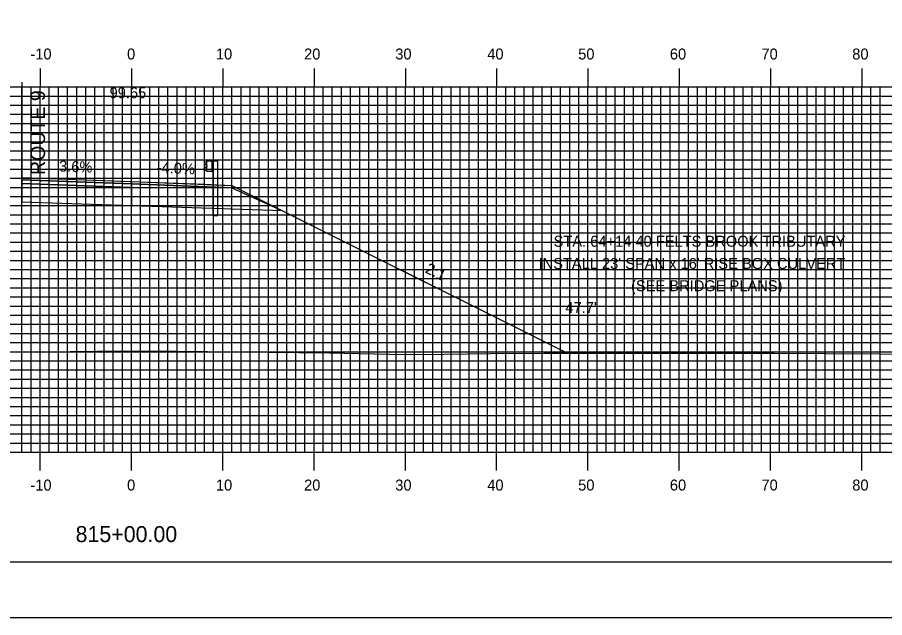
# Model space of a CAD drawing. Extents: x 2846 to 3190, y -1658 to -1438.
# Drawn here: x 2999.7 to 3094.7, y -1657.7 to -1592 of the extents above; entities that cross this region are included whole.
import ezdxf

# ---------------------------------------------------------------- set-up
doc = ezdxf.new("R2010")
doc.units = 0
for name, color, linetype in [('ANNOTATION', 7, 'Continuous'), ('BORDER', 7, 'Continuous'), ('D_Guardrail_Beam_Rt', 7, 'Continuous'), ('D_Roadway_Centerline', 7, 'Continuous'), ('D_Roadway_Centerline_Text', 7, 'Continuous'), ('D_Roadway_Edge_Shoulder', 7, 'Continuous'), ('D_Roadway_Edge_TW', 7, 'Continuous'), ('D_Roadway_Pavement', 7, 'Continuous'), ('D_Roadway_SlopeLines', 7, 'Continuous'), ('D_Roadway_SubGrade', 7, 'Continuous'), ('D_Text_Standard', 7, 'Continuous'), ('H_V ANNOTATION', 7, 'Continuous'), ('MAJOR', 7, 'Continuous'), ('MINOR', 7, 'Continuous'), ('PLOT BOUNDARY', 7, 'Continuous'), ('S_Roadway_Centerline', 7, 'Continuous')]:
    doc.layers.add(name, color=color, linetype=linetype)

msp = doc.modelspace()

# ---------------------------------------------------------------- linework, layer by layer
at = {"layer": 'BORDER'}
msp.add_lwpolyline([(2862.613, -1651.604), (3182.613, -1651.604), (3182.613, -1441.604), (2862.613, -1441.604)], close=True, dxfattribs=at)
at = {"layer": 'D_Guardrail_Beam_Rt'}
for p, q in [((3020.394, -1607.794), (3020.25, -1607.894)), ((3020.25, -1608.037), (3020.446, -1608.173)), ((3020.484, -1607.773), (3020.41, -1607.787)), ((3020.479, -1608.237), (3020.479, -1608.308)), ((3020.484, -1607.689), (3021.171, -1607.689)), ((3020.484, -1608.856), (3020.484, -1607.689)), ((3021.005, -1607.689), (3021.005, -1608.856)), ((3021.109, -1607.689), (3021.109, -1608.856)), ((3021.171, -1607.689), (3021.642, -1607.689)), ((3021.171, -1607.689), (3021.171, -1608.856)), ((3021.642, -1607.689), (3021.642, -1613.689)), ((3020.446, -1608.372), (3020.25, -1608.508)), ((3020.25, -1608.651), (3020.394, -1608.751)), ((3020.41, -1608.758), (3020.484, -1608.773)), ((3021.171, -1608.856), (3020.484, -1608.856)), ((3021.15, -1613.689), (3021.15, -1608.856)), ((3021.15, -1613.689), (3021.642, -1613.689))]:
    msp.add_line(p, q, dxfattribs=at)
for centre, major_axis, start_param, end_param in [((3020.301, -1607.965), (-0.0877, 0), 5.323254, 7.243116), ((3020.418, -1607.828), (-0.0417, 0), 4.907132, 5.323254), ((3020.4, -1608.237), (0.0789, 0), 0, 0.959931), ((3020.4, -1608.308), (0.0789, 0), 5.323254, 6.283185), ((3020.301, -1608.58), (-0.0877, 0), 5.323254, 7.243116), ((3020.418, -1608.717), (-0.0417, 0), 0.959931, 1.376053)]:
    msp.add_ellipse(centre, major_axis=major_axis, ratio=0.995501, start_param=start_param, end_param=end_param, dxfattribs=at)
at = {"layer": 'D_Roadway_Centerline'}
msp.add_lwpolyline([(3000.213, -1609.518), (3012.052, -1609.947), (3012.213, -1609.953), (3020.105, -1610.268), (3020.213, -1610.273), (3023.172, -1610.391), (3023.213, -1610.393), (3028.69, -1613.131), (3028.764, -1613.168), (3029.195, -1613.384), (3059.956, -1628.764)], dxfattribs=at)
at = {"layer": 'D_Roadway_Edge_Shoulder'}
for points in [[(3012.213, -1609.953), (3023.213, -1610.393), (3023.213, -1610.643), (3012.213, -1610.203)], [(3012.213, -1609.953), (3020.213, -1610.273), (3020.213, -1610.273), (3023.213, -1610.393), (3023.213, -1610.643), (3012.213, -1610.203)], [(3012.213, -1609.953), (3020.213, -1610.273), (3020.213, -1610.273), (3023.213, -1610.393), (3023.213, -1610.643), (3012.213, -1610.203)], [(3012.213, -1609.953), (3023.213, -1610.393), (3023.213, -1610.643), (3012.213, -1610.203)], [(3012.213, -1609.953), (3023.213, -1610.393), (3023.213, -1610.643), (3012.213, -1610.203)]]:
    msp.add_lwpolyline(points, close=True, dxfattribs=at)
at = {"layer": 'D_Roadway_Edge_TW'}
msp.add_lwpolyline([(3000.213, -1609.518), (3012.213, -1609.953), (3012.213, -1610.203), (3000.213, -1609.768)], close=True, dxfattribs=at)
msp.add_lwpolyline([(3000.213, -1609.518), (3012.213, -1609.953), (3012.213, -1610.203), (3000.213, -1609.768)], close=True, dxfattribs=at)
msp.add_lwpolyline([(3000.213, -1609.518), (3012.213, -1609.953), (3012.213, -1610.203), (3000.213, -1609.768)], close=True, dxfattribs=at)
msp.add_lwpolyline([(3000.213, -1609.518), (3012.213, -1609.953), (3012.213, -1610.203), (3000.213, -1609.768)], close=True, dxfattribs=at)
at = {"layer": 'D_Roadway_Pavement'}
msp.add_lwpolyline([(3000.213, -1609.768), (3012.213, -1610.203), (3012.213, -1610.619), (3000.213, -1610.185)], close=True, dxfattribs=at)
msp.add_lwpolyline([(3000.213, -1609.768), (3012.213, -1610.203), (3012.213, -1610.619), (3000.213, -1610.185)], close=True, dxfattribs=at)
msp.add_lwpolyline([(3000.213, -1609.768), (3012.213, -1610.203), (3012.213, -1610.619), (3000.213, -1610.185)], close=True, dxfattribs=at)
msp.add_lwpolyline([(3000.213, -1609.768), (3012.213, -1610.203), (3012.213, -1610.619), (3000.213, -1610.185)], close=True, dxfattribs=at)
msp.add_lwpolyline([(3012.213, -1610.203), (3012.213, -1610.619)], dxfattribs=at)
msp.add_lwpolyline([(3012.213, -1610.203), (3012.213, -1610.619)], dxfattribs=at)
msp.add_lwpolyline([(3012.213, -1610.203), (3012.213, -1610.619)], dxfattribs=at)
msp.add_lwpolyline([(3012.213, -1610.203), (3012.213, -1610.619)], dxfattribs=at)
msp.add_lwpolyline([(3012.213, -1610.203), (3012.213, -1610.619)], dxfattribs=at)
msp.add_lwpolyline([(3012.213, -1610.203), (3012.213, -1610.619)], dxfattribs=at)
msp.add_lwpolyline([(3012.213, -1610.203), (3012.213, -1610.619)], dxfattribs=at)
msp.add_lwpolyline([(3012.213, -1610.203), (3012.213, -1610.619)], dxfattribs=at)
msp.add_lwpolyline([(3012.213, -1610.203), (3012.213, -1610.619)], dxfattribs=at)
msp.add_lwpolyline([(3012.213, -1610.203), (3012.213, -1610.619)], dxfattribs=at)
msp.add_lwpolyline([(3012.213, -1610.203), (3012.213, -1610.619)], dxfattribs=at)
msp.add_lwpolyline([(3012.213, -1610.203), (3012.213, -1610.619)], dxfattribs=at)
msp.add_lwpolyline([(3012.213, -1610.203), (3012.213, -1610.619)], dxfattribs=at)
msp.add_lwpolyline([(3012.213, -1610.203), (3012.213, -1610.619)], dxfattribs=at)
at = {"layer": 'D_Roadway_SlopeLines'}
msp.add_lwpolyline([(3023.213, -1610.393), (3059.956, -1628.764)], dxfattribs=at)
msp.add_lwpolyline([(3023.213, -1610.393), (3059.956, -1628.764)], dxfattribs=at)
msp.add_lwpolyline([(3023.213, -1610.393), (3059.956, -1628.764)], dxfattribs=at)
msp.add_lwpolyline([(3023.213, -1610.393), (3059.956, -1628.764)], dxfattribs=at)
at = {"layer": 'D_Roadway_SubGrade'}
msp.add_line((3000.213, -1599.081), (3000.213, -1612.221), dxfattribs=at)
for points in [[(3000.213, -1610.185), (3012.213, -1610.619), (3012.213, -1612.619), (3000.213, -1612.221)], [(3000.213, -1610.185), (3012.213, -1610.619), (3012.213, -1612.619), (3000.213, -1612.221)], [(3000.213, -1610.185), (3012.213, -1610.619), (3012.213, -1612.619), (3000.213, -1612.221)], [(3000.213, -1610.185), (3012.213, -1610.619), (3012.213, -1612.619), (3000.213, -1612.221)], [(3012.213, -1610.619), (3012.213, -1610.203), (3023.213, -1610.643), (3023.213, -1610.393), (3028.764, -1613.168), (3012.213, -1612.619)], [(3012.213, -1610.619), (3012.213, -1610.203), (3023.213, -1610.643), (3023.213, -1610.393), (3028.764, -1613.168), (3012.213, -1612.619)], [(3012.213, -1610.619), (3012.213, -1610.203), (3023.213, -1610.643), (3023.213, -1610.393), (3028.764, -1613.168), (3012.213, -1612.619)], [(3012.213, -1610.619), (3012.213, -1610.203), (3023.213, -1610.643), (3028.764, -1613.168), (3012.213, -1612.619)], [(3012.213, -1610.619), (3012.213, -1610.203), (3023.213, -1610.643), (3023.213, -1610.393), (3028.764, -1613.168), (3012.213, -1612.619)]]:
    msp.add_lwpolyline(points, close=True, dxfattribs=at)
at = {"layer": 'MAJOR'}
for p, q in [((3002.213, -1597.6), (3002.213, -1599.604)), ((3012.213, -1597.6), (3012.213, -1599.604)), ((3022.213, -1597.6), (3022.213, -1599.604)), ((3032.213, -1597.6), (3032.213, -1599.604)), ((3042.213, -1597.6), (3042.213, -1599.604)), ((3052.213, -1597.6), (3052.213, -1599.604)), ((3062.213, -1597.6), (3062.213, -1599.604)), ((3072.213, -1597.6), (3072.213, -1599.604)), ((3082.213, -1597.6), (3082.213, -1599.604)), ((3092.213, -1597.6), (3092.213, -1599.604)), ((2872.213, -1599.604), (3152.213, -1599.604)), ((2872.213, -1599.604), (3152.213, -1599.604)), ((3002.213, -1639.604), (3002.213, -1599.604)), ((3012.213, -1639.604), (3012.213, -1599.604)), ((3022.213, -1639.604), (3022.213, -1599.604)), ((3032.213, -1639.604), (3032.213, -1599.604)), ((3042.213, -1639.604), (3042.213, -1599.604)), ((3052.213, -1639.604), (3052.213, -1599.604)), ((3062.213, -1639.604), (3062.213, -1599.604)), ((3072.213, -1639.604), (3072.213, -1599.604)), ((3082.213, -1639.604), (3082.213, -1599.604)), ((3092.213, -1639.604), (3092.213, -1599.604)), ((2872.213, -1604.604), (3152.213, -1604.604)), ((2872.213, -1609.604), (3152.213, -1609.604)), ((2872.213, -1614.604), (3152.213, -1614.604)), ((2872.213, -1619.604), (3152.213, -1619.604)), ((2872.213, -1624.604), (3152.213, -1624.604)), ((2872.213, -1629.604), (3152.213, -1629.604)), ((2872.213, -1634.604), (3152.213, -1634.604)), ((2872.213, -1639.604), (3152.213, -1639.604)), ((2872.213, -1639.604), (3152.213, -1639.604)), ((3002.213, -1641.608), (3002.213, -1639.604)), ((3012.213, -1641.608), (3012.213, -1639.604)), ((3022.213, -1641.608), (3022.213, -1639.604)), ((3032.213, -1641.608), (3032.213, -1639.604)), ((3042.213, -1641.608), (3042.213, -1639.604)), ((3052.213, -1641.608), (3052.213, -1639.604)), ((3062.213, -1641.608), (3062.213, -1639.604)), ((3072.213, -1641.608), (3072.213, -1639.604)), ((3082.213, -1641.608), (3082.213, -1639.604)), ((3092.213, -1641.608), (3092.213, -1639.604))]:
    msp.add_line(p, q, dxfattribs=at)
at = {"layer": 'MINOR'}
for p, q in [((3000.213, -1639.604), (3000.213, -1599.604)), ((3001.213, -1639.604), (3001.213, -1599.604)), ((3003.213, -1639.604), (3003.213, -1599.604)), ((3004.213, -1639.604), (3004.213, -1599.604)), ((3005.213, -1639.604), (3005.213, -1599.604)), ((3006.213, -1639.604), (3006.213, -1599.604)), ((3007.213, -1639.604), (3007.213, -1599.604)), ((3008.213, -1639.604), (3008.213, -1599.604)), ((3009.213, -1639.604), (3009.213, -1599.604)), ((3010.213, -1639.604), (3010.213, -1599.604)), ((3011.213, -1639.604), (3011.213, -1599.604)), ((3013.213, -1639.604), (3013.213, -1599.604)), ((3014.213, -1639.604), (3014.213, -1599.604)), ((3015.213, -1639.604), (3015.213, -1599.604)), ((3016.213, -1639.604), (3016.213, -1599.604)), ((3017.213, -1639.604), (3017.213, -1599.604)), ((3018.213, -1639.604), (3018.213, -1599.604)), ((3019.213, -1639.604), (3019.213, -1599.604)), ((3020.213, -1639.604), (3020.213, -1599.604)), ((3021.213, -1639.604), (3021.213, -1599.604)), ((3023.213, -1639.604), (3023.213, -1599.604)), ((3024.213, -1639.604), (3024.213, -1599.604)), ((3025.213, -1639.604), (3025.213, -1599.604)), ((3026.213, -1639.604), (3026.213, -1599.604)), ((3027.213, -1639.604), (3027.213, -1599.604)), ((3028.213, -1639.604), (3028.213, -1599.604)), ((3029.213, -1639.604), (3029.213, -1599.604)), ((3030.213, -1639.604), (3030.213, -1599.604)), ((3031.213, -1639.604), (3031.213, -1599.604)), ((3033.213, -1639.604), (3033.213, -1599.604)), ((3034.213, -1639.604), (3034.213, -1599.604)), ((3035.213, -1639.604), (3035.213, -1599.604)), ((3036.213, -1639.604), (3036.213, -1599.604)), ((3037.213, -1639.604), (3037.213, -1599.604)), ((3038.213, -1639.604), (3038.213, -1599.604)), ((3039.213, -1639.604), (3039.213, -1599.604)), ((3040.213, -1639.604), (3040.213, -1599.604)), ((3041.213, -1639.604), (3041.213, -1599.604)), ((3043.213, -1639.604), (3043.213, -1599.604)), ((3044.213, -1639.604), (3044.213, -1599.604)), ((3045.213, -1639.604), (3045.213, -1599.604)), ((3046.213, -1639.604), (3046.213, -1599.604)), ((3047.213, -1639.604), (3047.213, -1599.604)), ((3048.213, -1639.604), (3048.213, -1599.604)), ((3049.213, -1639.604), (3049.213, -1599.604)), ((3050.213, -1639.604), (3050.213, -1599.604)), ((3051.213, -1639.604), (3051.213, -1599.604)), ((3053.213, -1639.604), (3053.213, -1599.604)), ((3054.213, -1639.604), (3054.213, -1599.604)), ((3055.213, -1639.604), (3055.213, -1599.604)), ((3056.213, -1639.604), (3056.213, -1599.604)), ((3057.213, -1639.604), (3057.213, -1599.604)), ((3058.213, -1639.604), (3058.213, -1599.604)), ((3059.213, -1639.604), (3059.213, -1599.604)), ((3060.213, -1639.604), (3060.213, -1599.604)), ((3061.213, -1639.604), (3061.213, -1599.604)), ((3063.213, -1639.604), (3063.213, -1599.604)), ((3064.213, -1639.604), (3064.213, -1599.604)), ((3065.213, -1639.604), (3065.213, -1599.604)), ((3066.213, -1639.604), (3066.213, -1599.604)), ((3067.213, -1639.604), (3067.213, -1599.604)), ((3068.213, -1639.604), (3068.213, -1599.604)), ((3069.213, -1639.604), (3069.213, -1599.604)), ((3070.213, -1639.604), (3070.213, -1599.604)), ((3071.213, -1639.604), (3071.213, -1599.604)), ((3073.213, -1639.604), (3073.213, -1599.604)), ((3074.213, -1639.604), (3074.213, -1599.604)), ((3075.213, -1639.604), (3075.213, -1599.604)), ((3076.213, -1639.604), (3076.213, -1599.604)), ((3077.213, -1639.604), (3077.213, -1599.604)), ((3078.213, -1639.604), (3078.213, -1599.604)), ((3079.213, -1639.604), (3079.213, -1599.604)), ((3080.213, -1639.604), (3080.213, -1599.604)), ((3081.213, -1639.604), (3081.213, -1599.604)), ((3083.213, -1639.604), (3083.213, -1599.604)), ((3084.213, -1639.604), (3084.213, -1599.604)), ((3085.213, -1639.604), (3085.213, -1599.604)), ((3086.213, -1639.604), (3086.213, -1599.604)), ((3087.213, -1639.604), (3087.213, -1599.604)), ((3088.213, -1639.604), (3088.213, -1599.604)), ((3089.213, -1639.604), (3089.213, -1599.604)), ((3090.213, -1639.604), (3090.213, -1599.604)), ((3091.213, -1639.604), (3091.213, -1599.604)), ((3093.213, -1639.604), (3093.213, -1599.604)), ((3094.213, -1639.604), (3094.213, -1599.604)), ((2872.213, -1600.604), (3152.213, -1600.604)), ((2872.213, -1601.604), (3152.213, -1601.604)), ((2872.213, -1602.604), (3152.213, -1602.604)), ((2872.213, -1603.604), (3152.213, -1603.604)), ((2872.213, -1605.604), (3152.213, -1605.604)), ((2872.213, -1606.604), (3152.213, -1606.604)), ((2872.213, -1607.604), (3152.213, -1607.604)), ((2872.213, -1608.604), (3152.213, -1608.604)), ((2872.213, -1610.604), (3152.213, -1610.604)), ((2872.213, -1611.604), (3152.213, -1611.604)), ((2872.213, -1612.604), (3152.213, -1612.604)), ((2872.213, -1613.604), (3152.213, -1613.604)), ((2872.213, -1615.604), (3152.213, -1615.604)), ((2872.213, -1616.604), (3152.213, -1616.604)), ((2872.213, -1617.604), (3152.213, -1617.604)), ((2872.213, -1618.604), (3152.213, -1618.604)), ((2872.213, -1620.604), (3152.213, -1620.604)), ((2872.213, -1621.604), (3152.213, -1621.604)), ((2872.213, -1622.604), (3152.213, -1622.604)), ((2872.213, -1623.604), (3152.213, -1623.604)), ((2872.213, -1625.604), (3152.213, -1625.604)), ((2872.213, -1626.604), (3152.213, -1626.604)), ((2872.213, -1627.604), (3152.213, -1627.604)), ((2872.213, -1628.604), (3152.213, -1628.604)), ((2872.213, -1630.604), (3152.213, -1630.604)), ((2872.213, -1631.604), (3152.213, -1631.604)), ((2872.213, -1632.604), (3152.213, -1632.604)), ((2872.213, -1633.604), (3152.213, -1633.604)), ((2872.213, -1635.604), (3152.213, -1635.604)), ((2872.213, -1636.604), (3152.213, -1636.604)), ((2872.213, -1637.604), (3152.213, -1637.604)), ((2872.213, -1638.604), (3152.213, -1638.604))]:
    msp.add_line(p, q, dxfattribs=at)
at = {"layer": 'PLOT BOUNDARY'}
msp.add_lwpolyline([(2846.426, -1657.723), (3186.426, -1657.723), (3186.426, -1437.723), (2846.426, -1437.723)], close=True, dxfattribs=at)
at = {"layer": 'S_Roadway_Centerline'}
msp.add_lwpolyline([(2992.885, -1628.666), (3002.45, -1628.61), (3011.53, -1628.507), (3017.167, -1628.528), (3033.905, -1628.716), (3040.466, -1628.879), (3043.823, -1628.912), (3051.558, -1628.813), (3057.43, -1628.765), (3059.92, -1628.764), (3070.511, -1628.752), (3078.456, -1628.753), (3082.526, -1628.763), (3099.941, -1628.88)], dxfattribs=at)

# ---------------------------------------------------------------- texts
at = {"layer": 'ANNOTATION'}
for s, height, rotation, p in [('ROUTE 9', 1.6, 90, (3002.744, -1609.248)), ('3.6%', 1.2, 357.92822, (3004.264, -1608.864)), ('-4.0%', 1.2, 357.70938, (3014.949, -1609.016)), ('2:1', 1.2, 333.43495, (3044.294, -1619.897))]:
    msp.add_text(s, height=height, rotation=rotation, dxfattribs=at).set_placement(p)
for s, p in [('STA. 64+14.40 FELTS BROOK TRIBUTARY', (3058.451, -1617.106)), ("INSTALL 23' SPAN x 16' RISE BOX CULVERT", (3056.8, -1619.541)), ('(SEE BRIDGE PLANS)', (3066.937, -1621.976))]:
    msp.add_text(s, height=1.2, dxfattribs=at).set_placement(p)
at = {"layer": 'D_Roadway_Centerline_Text'}
msp.add_text('99.65', height=1.2, dxfattribs=at).set_placement((3009.81, -1600.847))
at = {"layer": 'D_Text_Standard'}
msp.add_text("47.7'", height=1.2, dxfattribs=at).set_placement((3059.744, -1624.358))
at = {"layer": 'H_V ANNOTATION'}
for s, height, p in [('-10', 1.2, (3001.143, -1596.604)), ('0', 1.2, (3011.731, -1596.604)), ('10', 1.2, (3021.464, -1596.604)), ('20', 1.2, (3031.121, -1596.604)), ('30', 1.2, (3041.11, -1596.604)), ('40', 1.2, (3051.185, -1596.604)), ('50', 1.2, (3061.142, -1596.604)), ('60', 1.2, (3071.185, -1596.604)), ('70', 1.2, (3081.217, -1596.604)), ('80', 1.2, (3091.164, -1596.604)), ('-10', 1.2, (3001.143, -1643.804)), ('0', 1.2, (3011.731, -1643.804)), ('10', 1.2, (3021.464, -1643.804)), ('20', 1.2, (3031.121, -1643.804)), ('30', 1.2, (3041.11, -1643.804)), ('40', 1.2, (3051.185, -1643.804)), ('50', 1.2, (3061.142, -1643.804)), ('60', 1.2, (3071.185, -1643.804)), ('70', 1.2, (3081.217, -1643.804)), ('80', 1.2, (3091.164, -1643.804)), ('815+00.00', 1.75, (3006.095, -1649.448))]:
    msp.add_text(s, height=height, dxfattribs=at).set_placement(p)

doc.saveas('drawing.dxf')
